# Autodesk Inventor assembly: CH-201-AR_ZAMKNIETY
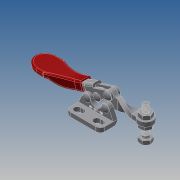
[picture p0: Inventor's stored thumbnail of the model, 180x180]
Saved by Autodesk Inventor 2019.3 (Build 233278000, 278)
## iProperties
Company: ·L?¤¤?
Created: 2010-06
Part Number: CH-201-AR_ZAMKNIETY
Material: Ogólny
Description: STEP AP203
Document SubType Name: Assembly
Designer: CADENGINEERING4
Sending System: SolidWorks 2005179
Preprocessor: SwSTEP 2.0
Title: CH-201-AR.STEP
Author: ·L?¥Î?
Revision Number: ANY
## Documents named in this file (8)
- E:\STRONA\Horizontal toggle clamp\CH-201-AR\CH-201-AR_ZAMKNIETY.iam
- E:\STRONA\Horizontal toggle clamp\CH-201-AR\201-AR-01___.ipt
- E:\STRONA\Horizontal toggle clamp\CH-201-AR\201-A-02___.ipt
- E:\STRONA\Horizontal toggle clamp\CH-201-AR\201-06___.ipt
- E:\STRONA\Horizontal toggle clamp\CH-201-AR\M4___.ipt
- E:\STRONA\Horizontal toggle clamp\CH-201-AR\201-03___.iam
- E:\STRONA\Horizontal toggle clamp\CH-201-AR\CH-SA-042007___.ipt
- E:\STRONA\Horizontal toggle clamp\CH-201-AR\201-A-04___.ipt
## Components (12 placed, 12 different names)
1. 201-AR-01_??_1 — Zestawiające:6, Zestawiające:7, Zestawiające:8, Zestawiające:16, Zestawiające:17, Zestawiające:20, Przejściowe:1
2. 201-A-02_??_2 — Zestawiające:1, Zestawiające:4, Zestawiające:5, Zestawiające:6, Zestawiające:22, Zestawiające:23
3. 201-06_??_3 — Zestawiające:7, Zestawiające:8, Zestawiające:22
4. 201-06_??_4 — Zestawiające:20, Zestawiające:21
5. M4_??_5 — Zestawiające:3, Zestawiające:5
6. M4_??_6 — Równoległe:1, Zestawiające:2, Zestawiające:4
7. 201-03_??_7 [sub-assembly] — Zestawiające:9, Zestawiające:10, Zestawiające:11, Zestawiające:12, Zestawiające:19, Przejściowe:1
8. 201-06_??_8 — Zestawiające:9, Zestawiające:12, Zestawiające:18
9. CH-SA-042007_??_9 — Równoległe:1, Zestawiające:1, Zestawiające:2, Zestawiające:3
10. 201-06_??_10 — Zestawiające:10, Zestawiające:11, Zestawiające:23
11. 201-A-04_??_11 — Zestawiające:13, Zestawiające:14, Zestawiające:15, Zestawiające:16, Zestawiające:18, Zestawiające:19, Zestawiające:21
12. 201-A-04_??_12 — Zestawiające:13, Zestawiające:14, Zestawiające:15, Zestawiające:17
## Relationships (25: Mate 23, Flush 1, Transitional 1)
- Równoległe:1 [Flush]: M4_??_6 ↔ CH-SA-042007_??_9
- Zestawiające:1 [Mate]: 201-A-02_??_2 ↔ CH-SA-042007_??_9
- Zestawiające:2 [Mate]: M4_??_6 ↔ CH-SA-042007_??_9
- Zestawiające:3 [Mate]: M4_??_5 ↔ CH-SA-042007_??_9
- Zestawiające:4 [Mate]: 201-A-02_??_2 ↔ M4_??_6
- Zestawiające:5 [Mate]: 201-A-02_??_2 ↔ M4_??_5
- Zestawiające:6 [Mate]: 201-AR-01_??_1 ↔ 201-A-02_??_2
- Zestawiające:7 [Mate]: 201-AR-01_??_1 ↔ 201-06_??_3
- Zestawiające:8 [Mate]: 201-AR-01_??_1 ↔ 201-06_??_3
- Zestawiające:9 [Mate]: 201-03_??_7 ↔ 201-06_??_8
- Zestawiające:10 [Mate]: 201-03_??_7 ↔ 201-06_??_10
- Zestawiające:11 [Mate]: 201-03_??_7 ↔ 201-06_??_10
- Zestawiające:12 [Mate]: 201-03_??_7 ↔ 201-06_??_8
- Zestawiające:13 [Mate]: 201-A-04_??_11 ↔ 201-A-04_??_12
- Zestawiające:14 [Mate]: 201-A-04_??_11 ↔ 201-A-04_??_12
- Zestawiające:15 [Mate]: 201-A-04_??_11 ↔ 201-A-04_??_12
- Zestawiające:16 [Mate]: 201-AR-01_??_1 ↔ 201-A-04_??_11
- Zestawiające:17 [Mate]: 201-AR-01_??_1 ↔ 201-A-04_??_12
- Zestawiające:18 [Mate]: 201-06_??_8 ↔ 201-A-04_??_11
- Zestawiające:19 [Mate]: 201-03_??_7 ↔ 201-A-04_??_11
- Zestawiające:20 [Mate]: 201-AR-01_??_1 ↔ 201-06_??_4
- Zestawiające:21 [Mate]: 201-06_??_4 ↔ 201-A-04_??_11
- Zestawiające:22 [Mate]: 201-A-02_??_2 ↔ 201-06_??_3
- Zestawiające:23 [Mate]: 201-A-02_??_2 ↔ 201-06_??_10
- Przejściowe:1 [Transitional]: 201-AR-01_??_1 ↔ 201-03_??_7
